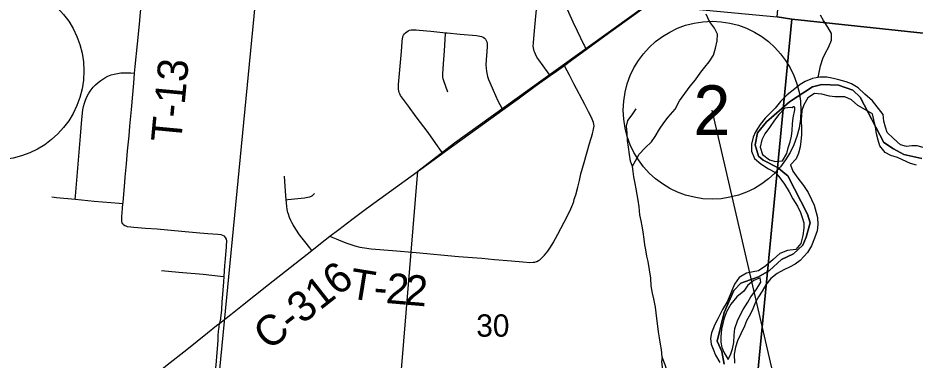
# Model space of a CAD drawing. Extents: x 0 to 1134, y 0 to 440.
# Drawn here: x 199 to 249.6, y 121.7 to 141 of the extents above; entities that cross this region are included whole.
import ezdxf

# ---------------------------------------------------------------- set-up
doc = ezdxf.new("R2010")
doc.units = 0
for name, color, linetype in [('GM_X_County_Road', 7, 'Continuous'), ('GM_X_County_Road_Text', 7, 'Continuous'), ('GM_X_Major_River', 7, 'Continuous'), ('GM_X_Minor_Lake', 7, 'Continuous'), ('GM_X_Minor_River', 7, 'Continuous'), ('GM_X_Rail_Line', 7, 'Continuous'), ('GM_X_Section', 7, 'Continuous'), ('GM_X_Section_Text', 7, 'Continuous'), ('GM_X_Township', 7, 'Continuous'), ('GM_X_Township_Road', 7, 'Continuous'), ('GM_X_Township_Road_Text', 7, 'Continuous'), ('SH_Data', 7, 'Continuous'), ('SH_Masking', 7, 'Continuous'), ('SH_Text', 7, 'Continuous')]:
    doc.layers.add(name, color=color, linetype=linetype)

msp = doc.modelspace()

# ---------------------------------------------------------------- linework, layer by layer
at = {"layer": 'GM_X_County_Road'}
for points in [[(231.036, 139.198), (232.09, 139.967), (234.507, 141.714), (236.616, 143.244), (236.866, 143.427)], [(229.803, 138.308), (230.206, 138.599), (231.036, 139.198)], [(229.013, 137.739), (229.224, 137.89), (229.803, 138.308)], [(222.96, 133.36), (223.118, 133.473), (224.854, 134.73), (226.331, 135.8), (227.194, 136.425), (228.165, 137.131), (229.013, 137.739)], [(216.607, 128.699), (217.105, 129.084), (217.842, 129.642), (218.66, 130.257), (219.413, 130.807), (222.06, 132.711), (222.96, 133.36)], [(215.588, 127.904), (216.073, 128.285), (216.607, 128.699)], [(210.396, 123.806), (211.026, 124.302), (211.681, 124.826), (213.143, 125.982), (215.588, 127.904)], [(201.679, 116.881), (201.811, 116.981), (202.417, 117.464), (203.291, 118.16), (204.822, 119.379), (205.844, 120.19), (206.719, 120.886), (207.447, 121.468), (208.544, 122.334), (209.709, 123.264), (210.221, 123.669), (210.396, 123.806)], [(210.107, 120.508), (210.207, 121.675), (210.228, 121.927), (210.265, 122.368), (210.302, 122.852), (210.319, 123.096), (210.334, 123.352), (210.357, 123.585), (210.368, 123.662), (210.396, 123.806)]]:
    msp.add_lwpolyline(points, dxfattribs=at)
at = {"layer": 'GM_X_Major_River'}
for points in [[(247.754, 135.535), (247.154, 136.307), (246.731, 136.683), (246.342, 137.047), (245.972, 137.273), (245.667, 137.384), (245.26, 137.497), (244.954, 137.574), (244.58, 137.652), (244.182, 137.652), (243.781, 137.571), (243.366, 137.4), (243.076, 137.225), (242.785, 136.983), (242.354, 136.652), (241.979, 136.275), (241.684, 135.895)], [(247.163, 135.584), (246.326, 136.044), (245.97, 136.361), (245.599, 136.531), (245.029, 136.546), (244.733, 136.566), (244.303, 136.68), (243.894, 136.725), (243.512, 136.473), (243.296, 136.08), (243.174, 135.775)], [(241.684, 135.895), (241.11, 135.338), (240.839, 134.98), (240.577, 134.565), (240.433, 134.261), (240.343, 133.876), (240.334, 133.489), (240.505, 133.075), (240.873, 132.769), (241.299, 132.496), (241.692, 132.281), (241.947, 131.99), (242.199, 131.619), (242.461, 131.191), (242.679, 130.798), (242.931, 130.393), (243.104, 130.035), (243.199, 129.748), (243.294, 129.449), (243.297, 129.153), (243.241, 128.733), (243.116, 128.291), (242.834, 127.957), (242.365, 127.889), (241.94, 127.729), (241.567, 127.385), (241.159, 127.03), (240.731, 126.756), (240.433, 126.695), (240.055, 126.625), (239.651, 126.385), (239.39, 125.993), (239.257, 125.688), (239.147, 125.395), (238.966, 125.012), (238.716, 124.585), (238.452, 124.056), (238.284, 123.73), (238.09, 123.257), (238.025, 122.939), (238.063, 122.631), (238.192, 122.342), (238.309, 122.009), (238.56, 121.592)], [(242.787, 135.809), (242.79, 135.934), (242.746, 135.969), (242.712, 135.982), (242.631, 135.927), (242.516, 135.936), (242.217, 135.891)], [(243.174, 135.775), (243.134, 135.23), (243.156, 134.74), (243.159, 134.409), (243.127, 134.045), (243.084, 133.727), (242.995, 133.365), (242.862, 133.049), (242.534, 132.704), (242.673, 132.348), (242.959, 131.964), (243.268, 131.558), (243.543, 131.163), (243.726, 130.771), (243.866, 130.437), (243.992, 130.035), (244.053, 129.749), (244.077, 129.35), (244.034, 129.009), (243.898, 128.591), (243.716, 128.151), (243.502, 127.78), (243.092, 127.335), (242.801, 127.126), (242.478, 126.952), (242.167, 126.8), (241.786, 126.593), (241.437, 126.317), (241.143, 125.96), (240.94, 125.6), (240.739, 125.286), (240.571, 124.983), (240.425, 124.622), (240.293, 124.329), (240.055, 123.948), (239.945, 123.643), (239.74, 123.215), (239.559, 122.809), (239.448, 122.459), (239.369, 122.073), (239.379, 121.56)], [(242.217, 135.891), (241.89, 135.546), (241.642, 135.234), (241.347, 134.819), (241.087, 134.461), (240.931, 134.124), (240.84, 133.704), (240.966, 133.291), (241.357, 132.996), (241.696, 132.896), (242.096, 132.943), (242.335, 133.359), (242.411, 133.665), (242.511, 134.015), (242.587, 134.321), (242.629, 134.639), (242.65, 135.014), (242.693, 135.355), (242.787, 135.809)], [(249.64, 132.696), (249.29, 132.784), (248.851, 133.001), (248.558, 133.122), (248.185, 133.234), (247.871, 133.401), (247.561, 133.774), (247.467, 134.095), (247.385, 134.45), (247.327, 134.851), (247.234, 135.24), (247.163, 135.584)], [(252.095, 135.73), (252.083, 135.141), (252.019, 134.835), (251.929, 134.461), (251.852, 134.098), (251.74, 133.725), (251.458, 133.402), (251.069, 133.343), (250.741, 133.42), (250.413, 133.519), (250.008, 133.689), (249.668, 133.789), (249.372, 133.774), (249.075, 133.736), (248.736, 133.835), (248.346, 134.187), (247.979, 134.538), (247.896, 134.825), (247.791, 135.169), (247.754, 135.535)], [(240.823, 126.367), (240.466, 126.205), (240.14, 125.939), (239.915, 125.603), (239.52, 125.283), (239.179, 124.87), (238.941, 124.454), (238.806, 124.082), (238.719, 123.788), (238.654, 123.47), (238.608, 123.038), (238.612, 122.742), (238.673, 122.433), (238.802, 122.133), (239.031, 121.774), (239.172, 122.08), (239.269, 122.369), (239.34, 122.724), (239.362, 123.133), (239.406, 123.508), (239.554, 123.937), (239.687, 124.23), (239.866, 124.579), (240.127, 124.983), (240.306, 125.286), (240.612, 125.688)], [(240.612, 125.688), (240.873, 126.118), (240.823, 126.367)]]:
    msp.add_lwpolyline(points, dxfattribs=at)
at = {"layer": 'GM_X_Minor_Lake'}
for points in [[(235.309, 121.889), (235.271, 121.627), (235.313, 121.354), (235.343, 121.103), (235.373, 120.818), (235.403, 120.544), (235.434, 120.304), (235.476, 120.042), (235.518, 119.791), (235.525, 119.506), (235.555, 119.244), (235.518, 119.005), (235.514, 118.755), (235.636, 118.514), (235.781, 118.473)], [(235.781, 118.473), (235.885, 118.442), (235.957, 118.715), (235.847, 118.944), (235.771, 119.241), (235.763, 119.469), (235.755, 119.662), (235.736, 119.924), (235.716, 120.164), (235.674, 120.404), (235.644, 120.666), (235.602, 120.94), (235.55, 121.225), (235.485, 121.465), (235.309, 121.889)]]:
    msp.add_lwpolyline(points, dxfattribs=at)
at = {"layer": 'GM_X_Minor_River'}
for points in [[(236.035, 135.852), (236.28, 136.304), (236.581, 136.733), (236.893, 137.128), (237.182, 137.489), (237.483, 137.918), (237.714, 138.211), (237.968, 138.504), (238.2, 138.876), (238.319, 139.273), (238.415, 139.682), (238.42, 140.069), (238.264, 140.39), (237.985, 140.781), (237.785, 141.182)], [(244.077, 137.631), (244.124, 137.709), (244.173, 137.993), (244.233, 138.288), (244.352, 138.697), (244.516, 139.013), (244.679, 139.307), (244.854, 139.715), (244.848, 140.102), (244.647, 140.446), (244.39, 140.837), (244.223, 141.124)], [(235.309, 121.889), (235.27, 122.322), (235.217, 122.619), (235.154, 122.984), (235.102, 123.315), (235.061, 123.634), (235.01, 124.067), (234.97, 124.398), (234.929, 124.717), (234.844, 125.185), (234.769, 125.505), (234.684, 125.905), (234.668, 126.349), (234.595, 126.805), (234.522, 127.273), (234.458, 127.582), (234.383, 127.924), (234.33, 128.221), (234.301, 128.54), (234.25, 128.939), (234.186, 129.259), (234.122, 129.556), (234.059, 129.91), (234.02, 130.354), (233.957, 130.731), (233.905, 131.05), (233.841, 131.358), (233.788, 131.655), (233.714, 132.043), (233.673, 132.329), (233.643, 132.614), (233.533, 132.922), (233.471, 133.299), (233.408, 133.71), (233.357, 134.086), (233.34, 134.508), (233.3, 134.884), (233.384, 135.201), (233.616, 135.528), (233.853, 135.853)], [(233.636, 132.632), (233.807, 132.941), (234.017, 133.314), (234.363, 133.662), (234.72, 133.999), (234.918, 134.303), (235.163, 134.71), (235.407, 135.071), (235.65, 135.398), (236.035, 135.852)]]:
    msp.add_lwpolyline(points, dxfattribs=at)
at = {"layer": 'GM_X_Rail_Line'}
msp.add_lwpolyline([(218.648, 83.037), (217.883, 83.933), (216.691, 85.332), (215.218, 87.758), (215.044, 89.058), (215.997, 90.271), (218.076, 91.484), (219.982, 93.131), (221.022, 95.038), (221.282, 97.031), (220.935, 97.724), (218.769, 98.677), (221.544, 132.36), (223.618, 133.946), (235.537, 142.526)], dxfattribs=at)
at = {"layer": 'GM_X_Section'}
for points in [[(244.499, 171.089), (274.425, 167.918), (271.323, 137.84), (242.613, 140.903), (241.786, 141.042)], [(212.603, 143.785), (241.786, 141.042), (242.613, 140.903), (239.744, 111.129), (209.686, 113.866)], [(242.613, 140.903), (271.323, 137.84), (273.637, 137.644), (270.808, 108.206), (239.744, 111.129)]]:
    msp.add_lwpolyline(points, close=True, dxfattribs=at)
at = {"layer": 'GM_X_Township'}
for points in [[(238.81, 121.498), (238.676, 122.213), (238.408, 122.794), (238.81, 124.403), (239.346, 125.655), (239.749, 126.057), (240.732, 126.414), (241.358, 126.772), (242.029, 127.398), (242.699, 127.711), (243.235, 128.203), (243.414, 128.65), (243.638, 129.454), (243.503, 129.945), (242.386, 132.09), (242.131, 132.302), (241.849, 132.537), (241, 132.984), (240.732, 133.207), (240.553, 133.833), (240.687, 134.504), (241.179, 135.13), (242.474, 136.247), (243.771, 137.096), (244.307, 137.23), (245.246, 137.186), (246.051, 136.918), (246.453, 136.516), (247.795, 133.968), (248.331, 133.611), (248.913, 133.298), (249.941, 133.075)], [(249.941, 133.075), (248.913, 133.298), (248.331, 133.611), (247.795, 133.968), (246.453, 136.516), (246.051, 136.918), (245.246, 137.186), (244.307, 137.23), (243.771, 137.096), (242.474, 136.247), (241.179, 135.13), (240.687, 134.504), (240.553, 133.833), (240.732, 133.207), (241, 132.984), (241.849, 132.537), (242.131, 132.302), (242.386, 132.09), (243.503, 129.945), (243.638, 129.454), (243.414, 128.65), (243.235, 128.203), (242.699, 127.711), (242.029, 127.398), (241.358, 126.772), (240.732, 126.414), (239.749, 126.057), (239.346, 125.655), (238.81, 124.403), (238.408, 122.794), (238.676, 122.213), (238.81, 121.498)]]:
    msp.add_lwpolyline(points, dxfattribs=at)
at = {"layer": 'GM_X_Township_Road'}
for points in [[(205.602, 137.87), (205.634, 138.234), (205.759, 139.527), (205.873, 140.633), (205.941, 141.278), (206.013, 141.925), (206.107, 142.849), (206.233, 144.146), (206.257, 144.39)], [(229.013, 137.739), (228.858, 137.949), (228.366, 138.617), (228.261, 138.771), (228.173, 138.937), (228.136, 139.023), (228.104, 139.112), (228.08, 139.203), (228.065, 139.297), (228.057, 139.391), (228.06, 139.578), (228.098, 140.038), (228.182, 140.863), (228.32, 142.227), (228.327, 142.29)], [(228.327, 142.29), (228.667, 142.261), (229.037, 142.22), (229.223, 142.191), (229.315, 142.171), (229.407, 142.145), (229.496, 142.109), (229.58, 142.06), (229.655, 141.997), (229.719, 141.925), (229.774, 141.847), (229.867, 141.682), (230.289, 140.749), (230.525, 140.244), (230.888, 139.491), (230.93, 139.408), (231.036, 139.198)], [(222.96, 133.36), (222.887, 133.464), (222.567, 133.92), (222.133, 134.524), (221.467, 135.42), (221.023, 136.017), (220.797, 136.311), (220.685, 136.462), (220.581, 136.616), (220.534, 136.702), (220.504, 136.788), (220.484, 136.874), (220.466, 136.96), (220.46, 137.051), (220.463, 137.238), (220.552, 138.259), (220.629, 139.091), (220.674, 139.637), (220.691, 139.83), (220.7, 139.881), (220.711, 139.922), (220.75, 140.011), (220.794, 140.076), (220.853, 140.138), (220.927, 140.2), (221.013, 140.25), (221.09, 140.283), (221.176, 140.301), (221.268, 140.313), (221.362, 140.313), (221.451, 140.31), (221.632, 140.295), (222.29, 140.224), (223.125, 140.135)], [(223.238, 136.797), (223.013, 137.437), (222.978, 137.552), (222.963, 137.644), (222.957, 137.75), (222.96, 137.83), (222.975, 138.111), (222.993, 138.386), (223.047, 139.125), (223.12, 140.072), (223.125, 140.135)], [(223.125, 140.135), (223.199, 140.127), (223.939, 140.058), (224.862, 139.981), (225.048, 139.957), (225.143, 139.931), (225.226, 139.892), (225.3, 139.845), (225.359, 139.777), (225.403, 139.706), (225.43, 139.626), (225.45, 139.541), (225.459, 139.453), (225.459, 139.362), (225.437, 139.086), (225.398, 138.622), (225.39, 138.341), (225.394, 138.152), (225.415, 137.963), (225.483, 137.69), (225.541, 137.513), (225.607, 137.337), (225.791, 136.909), (226.064, 136.318), (226.282, 135.894), (226.331, 135.8)], [(216.607, 128.699), (216.679, 128.668), (216.954, 128.551), (217.214, 128.443), (217.564, 128.313), (218.009, 128.167), (218.28, 128.092), (218.556, 128.038), (218.928, 127.993), (220.129, 127.887), (221.457, 127.775), (223.84, 127.564), (225.154, 127.458), (225.876, 127.398), (226.826, 127.313), (227.474, 127.256), (227.855, 127.229), (228.044, 127.234), (228.139, 127.247), (228.233, 127.274), (228.26, 127.285), (228.339, 127.325), (228.418, 127.378), (228.492, 127.438), (228.562, 127.502), (228.691, 127.639), (228.868, 127.859), (229.029, 128.091), (229.17, 128.331), (229.445, 128.816), (229.97, 129.812), (230.177, 130.232), (230.286, 130.492), (230.336, 130.657), (230.362, 130.775), (230.445, 131.032), (230.561, 131.456), (230.661, 131.837), (230.74, 132.207), (230.913, 132.837), (231.227, 133.911), (231.383, 134.449), (231.454, 134.72), (231.472, 134.815), (231.476, 134.912), (231.466, 135.009), (231.443, 135.103), (231.413, 135.193), (231.377, 135.281), (231.335, 135.366), (231.16, 135.695), (230.952, 136.112), (230.339, 137.26), (230.085, 137.758), (229.835, 138.244), (229.803, 138.308)], [(202.254, 130.774), (202.27, 130.955), (202.559, 134.327), (202.635, 135.255), (202.695, 135.811), (202.729, 135.997), (202.778, 136.178), (202.839, 136.356), (202.912, 136.53), (203, 136.697), (203.103, 136.855), (203.277, 137.076), (203.407, 137.213), (203.548, 137.338), (203.697, 137.453), (203.932, 137.607), (204.099, 137.697), (204.275, 137.766), (204.456, 137.818), (204.641, 137.856), (204.827, 137.88), (205.015, 137.889), (205.296, 137.886), (205.39, 137.881), (205.602, 137.87)], [(204.949, 130.541), (204.954, 130.588), (205.057, 131.747), (205.082, 132.024), (205.146, 132.765), (205.213, 133.506), (205.297, 134.339), (205.343, 134.895), (205.421, 135.822), (205.554, 137.307), (205.602, 137.87)], [(214.145, 130.75), (214.095, 131.233), (214.076, 131.514), (214.037, 132.079)], [(200.952, 130.906), (201.197, 130.88), (202.254, 130.774)], [(214.145, 130.75), (214.229, 130.759), (215.178, 130.856), (215.368, 130.886), (215.466, 130.907), (215.518, 130.929), (215.558, 130.948), (215.582, 130.962), (215.607, 130.977), (215.641, 131.007), (215.73, 131.099)], [(202.254, 130.774), (203.318, 130.667), (204.726, 130.558), (204.91, 130.544), (204.949, 130.541)], [(210.647, 126.44), (210.694, 127.053), (210.708, 127.239), (210.721, 127.424), (210.759, 127.887), (210.774, 128.065), (210.783, 128.159), (210.786, 128.244), (210.792, 128.348), (210.792, 128.44), (210.776, 128.539), (210.731, 128.629), (210.66, 128.701), (210.57, 128.748), (210.475, 128.771), (210.288, 128.787), (210.011, 128.806), (209.734, 128.834), (209.271, 128.873), (208.253, 128.96), (206.866, 129.088), (206.216, 129.138), (205.57, 129.187), (205.389, 129.202), (205.213, 129.234), (205.128, 129.257), (205.046, 129.29), (204.981, 129.338), (204.956, 129.369), (204.936, 129.394), (204.908, 129.448), (204.888, 129.531), (204.88, 129.619), (204.884, 129.801), (204.928, 130.263), (204.949, 130.541)], [(215.588, 127.904), (215.474, 128.047), (215.181, 128.411), (214.897, 128.785), (214.683, 129.094), (214.535, 129.335), (214.46, 129.466), (214.403, 129.583), (214.329, 129.754), (214.271, 129.933), (214.241, 130.031), (214.22, 130.114), (214.202, 130.206), (214.179, 130.392), (214.145, 130.75)], [(207.126, 126.763), (208.091, 126.682), (209.463, 126.561), (210.445, 126.461), (210.647, 126.44)], [(210.396, 123.806), (210.447, 123.979), (210.456, 124.03), (210.466, 124.096), (210.51, 124.56), (210.543, 125.019), (210.555, 125.204), (210.624, 126.126), (210.647, 126.44)]]:
    msp.add_lwpolyline(points, dxfattribs=at)
at = {"layer": 'SH_Data'}
msp.add_line((242.916, 115.149), (238.12, 135.784), dxfattribs=at)
at = {"layer": 'SH_Masking'}
for centre in [(197.75, 137.992), (238.12, 135.784)]:
    msp.add_circle(centre, 5, dxfattribs=at)
at = {"layer": 'SH_Text'}
for centre in [(197.75, 137.992), (238.12, 135.784)]:
    msp.add_circle(centre, 5, dxfattribs=at)

# ---------------------------------------------------------------- texts
at = {"layer": 'GM_X_County_Road_Text'}
msp.add_text('C-316', height=1.7045, rotation=38.2338, dxfattribs=at).set_placement((213.162, 122.231))
at = {"layer": 'GM_X_Section_Text'}
msp.add_text('30', height=1.2557, rotation=0, dxfattribs=at).set_placement((224.844, 123.049))
at = {"layer": 'GM_X_Township_Road_Text'}
for s, height, rotation, p in [('T-13', 1.7045, 84.6178, (208.219, 133.931)), ('T', 1.705, 350.7892, (217.621, 125.228)), ('2', 1.705, 355.0605, (219.718, 124.948)), ('2', 1.705, 355.1006, (220.765, 124.858)), ('-', 1.705, 355.2133, (219.022, 125.007))]:
    msp.add_text(s, height=height, rotation=rotation, dxfattribs=at).set_placement(p)
at = {"layer": 'SH_Text'}
msp.add_text('2', height=2.8, dxfattribs=at).set_placement((237.075, 134.384))

doc.saveas('drawing.dxf')
